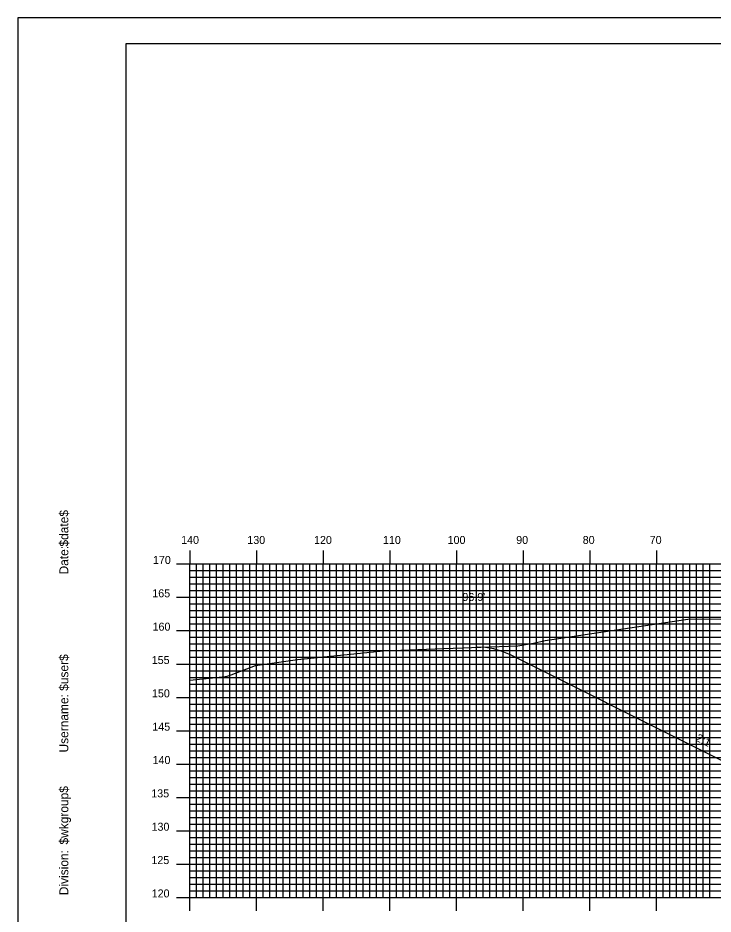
# Model space of a CAD drawing. Extents: x 1785008 to 1785352, y 442591 to 442811.
# Drawn here: x 1785008.2 to 1785112.5, y 442676.2 to 442810.5 of the extents above; entities that cross this region are included whole.
import ezdxf

# ---------------------------------------------------------------- set-up
doc = ezdxf.new("R2010")
doc.units = 0
for name, color, linetype in [('ANNOTATION', 7, 'Continuous'), ('BORDER', 7, 'Continuous'), ('D_Roadway_SlopeLines', 7, 'Continuous'), ('D_Text_Standard', 7, 'Continuous'), ('H_V ANNOTATION', 7, 'Continuous'), ('MAJOR', 7, 'Continuous'), ('MINOR', 7, 'Continuous'), ('PLOT BOUNDARY', 7, 'Continuous'), ('S_Roadway_Centerline', 7, 'Continuous')]:
    doc.layers.add(name, color=color, linetype=linetype)

msp = doc.modelspace()

# ---------------------------------------------------------------- linework, layer by layer
at = {"layer": 'BORDER'}
msp.add_lwpolyline([(1785024.43, 442596.67), (1785344.43, 442596.67), (1785344.43, 442806.67), (1785024.43, 442806.67)], close=True, dxfattribs=at)
at = {"layer": 'D_Roadway_SlopeLines'}
msp.add_lwpolyline([(1785139.85, 442686.16), (1785082.14, 442715.02), (1785080.89, 442715.56), (1785079.64, 442715.93), (1785078.39, 442716.14), (1785077.14, 442716.18)], dxfattribs=at)
at = {"layer": 'MAJOR'}
for p, q in [((1785034.03, 442730.67), (1785034.03, 442728.67)), ((1785044.03, 442730.67), (1785044.03, 442728.67)), ((1785054.03, 442730.67), (1785054.03, 442728.67)), ((1785064.03, 442730.67), (1785064.03, 442728.67)), ((1785074.03, 442730.67), (1785074.03, 442728.67)), ((1785084.03, 442730.67), (1785084.03, 442728.67)), ((1785094.03, 442730.67), (1785094.03, 442728.67)), ((1785104.03, 442730.67), (1785104.03, 442728.67)), ((1785032.02, 442728.67), (1785034.03, 442728.67)), ((1785034.03, 442728.67), (1785314.03, 442728.67)), ((1785034.03, 442678.67), (1785034.03, 442728.67)), ((1785034.03, 442678.67), (1785034.03, 442728.67)), ((1785034.03, 442728.67), (1785314.03, 442728.67)), ((1785044.03, 442678.67), (1785044.03, 442728.67)), ((1785054.03, 442678.67), (1785054.03, 442728.67)), ((1785064.03, 442678.67), (1785064.03, 442728.67)), ((1785074.03, 442678.67), (1785074.03, 442728.67)), ((1785084.03, 442678.67), (1785084.03, 442728.67)), ((1785094.03, 442678.67), (1785094.03, 442728.67)), ((1785104.03, 442678.67), (1785104.03, 442728.67)), ((1785032.02, 442723.67), (1785034.03, 442723.67)), ((1785034.03, 442723.67), (1785314.03, 442723.67)), ((1785032.02, 442718.67), (1785034.03, 442718.67)), ((1785034.03, 442718.67), (1785314.03, 442718.67)), ((1785032.02, 442713.67), (1785034.03, 442713.67)), ((1785034.03, 442713.67), (1785314.03, 442713.67)), ((1785032.02, 442708.67), (1785034.03, 442708.67)), ((1785034.03, 442708.67), (1785314.03, 442708.67)), ((1785032.02, 442703.67), (1785034.03, 442703.67)), ((1785034.03, 442703.67), (1785314.03, 442703.67)), ((1785032.02, 442698.67), (1785034.03, 442698.67)), ((1785034.03, 442698.67), (1785314.03, 442698.67)), ((1785032.02, 442693.67), (1785034.03, 442693.67)), ((1785034.03, 442693.67), (1785314.03, 442693.67)), ((1785032.02, 442688.67), (1785034.03, 442688.67)), ((1785034.03, 442688.67), (1785314.03, 442688.67)), ((1785032.02, 442683.67), (1785034.03, 442683.67)), ((1785034.03, 442683.67), (1785314.03, 442683.67)), ((1785032.02, 442678.67), (1785034.03, 442678.67)), ((1785034.03, 442678.67), (1785314.03, 442678.67)), ((1785034.03, 442678.67), (1785314.03, 442678.67)), ((1785034.03, 442676.66), (1785034.03, 442678.67)), ((1785044.03, 442676.66), (1785044.03, 442678.67)), ((1785054.03, 442676.66), (1785054.03, 442678.67)), ((1785064.03, 442676.66), (1785064.03, 442678.67)), ((1785074.03, 442676.66), (1785074.03, 442678.67)), ((1785084.03, 442676.66), (1785084.03, 442678.67)), ((1785094.03, 442676.66), (1785094.03, 442678.67)), ((1785104.03, 442676.66), (1785104.03, 442678.67))]:
    msp.add_line(p, q, dxfattribs=at)
at = {"layer": 'MINOR'}
for p, q in [((1785035.03, 442678.67), (1785035.03, 442728.67)), ((1785036.03, 442678.67), (1785036.03, 442728.67)), ((1785037.03, 442678.67), (1785037.03, 442728.67)), ((1785038.03, 442678.67), (1785038.03, 442728.67)), ((1785039.03, 442678.67), (1785039.03, 442728.67)), ((1785040.03, 442678.67), (1785040.03, 442728.67)), ((1785041.03, 442678.67), (1785041.03, 442728.67)), ((1785042.03, 442678.67), (1785042.03, 442728.67)), ((1785043.03, 442678.67), (1785043.03, 442728.67)), ((1785045.03, 442678.67), (1785045.03, 442728.67)), ((1785046.03, 442678.67), (1785046.03, 442728.67)), ((1785047.03, 442678.67), (1785047.03, 442728.67)), ((1785048.03, 442678.67), (1785048.03, 442728.67)), ((1785049.03, 442678.67), (1785049.03, 442728.67)), ((1785050.03, 442678.67), (1785050.03, 442728.67)), ((1785051.03, 442678.67), (1785051.03, 442728.67)), ((1785052.03, 442678.67), (1785052.03, 442728.67)), ((1785053.03, 442678.67), (1785053.03, 442728.67)), ((1785055.03, 442678.67), (1785055.03, 442728.67)), ((1785056.03, 442678.67), (1785056.03, 442728.67)), ((1785057.03, 442678.67), (1785057.03, 442728.67)), ((1785058.03, 442678.67), (1785058.03, 442728.67)), ((1785059.03, 442678.67), (1785059.03, 442728.67)), ((1785060.03, 442678.67), (1785060.03, 442728.67)), ((1785061.03, 442678.67), (1785061.03, 442728.67)), ((1785062.03, 442678.67), (1785062.03, 442728.67)), ((1785063.03, 442678.67), (1785063.03, 442728.67)), ((1785065.03, 442678.67), (1785065.03, 442728.67)), ((1785066.03, 442678.67), (1785066.03, 442728.67)), ((1785067.03, 442678.67), (1785067.03, 442728.67)), ((1785068.03, 442678.67), (1785068.03, 442728.67)), ((1785069.03, 442678.67), (1785069.03, 442728.67)), ((1785070.03, 442678.67), (1785070.03, 442728.67)), ((1785071.03, 442678.67), (1785071.03, 442728.67)), ((1785072.03, 442678.67), (1785072.03, 442728.67)), ((1785073.03, 442678.67), (1785073.03, 442728.67)), ((1785075.03, 442678.67), (1785075.03, 442728.67)), ((1785076.03, 442678.67), (1785076.03, 442728.67)), ((1785077.03, 442678.67), (1785077.03, 442728.67)), ((1785078.03, 442678.67), (1785078.03, 442728.67)), ((1785079.03, 442678.67), (1785079.03, 442728.67)), ((1785080.03, 442678.67), (1785080.03, 442728.67)), ((1785081.03, 442678.67), (1785081.03, 442728.67)), ((1785082.03, 442678.67), (1785082.03, 442728.67)), ((1785083.03, 442678.67), (1785083.03, 442728.67)), ((1785085.03, 442678.67), (1785085.03, 442728.67)), ((1785086.03, 442678.67), (1785086.03, 442728.67)), ((1785087.03, 442678.67), (1785087.03, 442728.67)), ((1785088.03, 442678.67), (1785088.03, 442728.67)), ((1785089.03, 442678.67), (1785089.03, 442728.67)), ((1785090.03, 442678.67), (1785090.03, 442728.67)), ((1785091.03, 442678.67), (1785091.03, 442728.67)), ((1785092.03, 442678.67), (1785092.03, 442728.67)), ((1785093.03, 442678.67), (1785093.03, 442728.67)), ((1785095.03, 442678.67), (1785095.03, 442728.67)), ((1785096.03, 442678.67), (1785096.03, 442728.67)), ((1785097.03, 442678.67), (1785097.03, 442728.67)), ((1785098.03, 442678.67), (1785098.03, 442728.67)), ((1785099.03, 442678.67), (1785099.03, 442728.67)), ((1785100.03, 442678.67), (1785100.03, 442728.67)), ((1785101.03, 442678.67), (1785101.03, 442728.67)), ((1785102.03, 442678.67), (1785102.03, 442728.67)), ((1785103.03, 442678.67), (1785103.03, 442728.67)), ((1785105.03, 442678.67), (1785105.03, 442728.67)), ((1785106.03, 442678.67), (1785106.03, 442728.67)), ((1785107.03, 442678.67), (1785107.03, 442728.67)), ((1785108.03, 442678.67), (1785108.03, 442728.67)), ((1785109.03, 442678.67), (1785109.03, 442728.67)), ((1785110.03, 442678.67), (1785110.03, 442728.67)), ((1785111.03, 442678.67), (1785111.03, 442728.67)), ((1785112.03, 442678.67), (1785112.03, 442728.67)), ((1785034.03, 442727.67), (1785314.03, 442727.67)), ((1785034.03, 442727.67), (1785036.03, 442727.67)), ((1785034.03, 442726.67), (1785314.03, 442726.67)), ((1785034.03, 442726.67), (1785036.03, 442726.67)), ((1785034.03, 442725.67), (1785314.03, 442725.67)), ((1785034.03, 442725.67), (1785036.03, 442725.67)), ((1785034.03, 442724.67), (1785314.03, 442724.67)), ((1785034.03, 442724.67), (1785036.03, 442724.67)), ((1785034.03, 442722.67), (1785314.03, 442722.67)), ((1785034.03, 442722.67), (1785036.03, 442722.67)), ((1785034.03, 442721.67), (1785314.03, 442721.67)), ((1785034.03, 442721.67), (1785036.03, 442721.67)), ((1785034.03, 442720.67), (1785314.03, 442720.67)), ((1785034.03, 442720.67), (1785036.03, 442720.67)), ((1785034.03, 442719.67), (1785314.03, 442719.67)), ((1785034.03, 442719.67), (1785036.03, 442719.67)), ((1785034.03, 442717.67), (1785314.03, 442717.67)), ((1785034.03, 442717.67), (1785036.03, 442717.67)), ((1785034.03, 442716.67), (1785314.03, 442716.67)), ((1785034.03, 442716.67), (1785036.03, 442716.67)), ((1785034.03, 442715.67), (1785314.03, 442715.67)), ((1785034.03, 442715.67), (1785036.03, 442715.67)), ((1785034.03, 442714.67), (1785314.03, 442714.67)), ((1785034.03, 442714.67), (1785036.03, 442714.67)), ((1785034.03, 442712.67), (1785314.03, 442712.67)), ((1785034.03, 442712.67), (1785036.03, 442712.67)), ((1785034.03, 442711.67), (1785314.03, 442711.67)), ((1785034.03, 442711.67), (1785036.03, 442711.67)), ((1785034.03, 442710.67), (1785314.03, 442710.67)), ((1785034.03, 442710.67), (1785036.03, 442710.67)), ((1785034.03, 442709.67), (1785314.03, 442709.67)), ((1785034.03, 442709.67), (1785036.03, 442709.67)), ((1785034.03, 442707.67), (1785314.03, 442707.67)), ((1785034.03, 442707.67), (1785036.03, 442707.67)), ((1785034.03, 442706.67), (1785314.03, 442706.67)), ((1785034.03, 442706.67), (1785036.03, 442706.67)), ((1785034.03, 442705.67), (1785314.03, 442705.67)), ((1785034.03, 442705.67), (1785036.03, 442705.67)), ((1785034.03, 442704.67), (1785314.03, 442704.67)), ((1785034.03, 442704.67), (1785036.03, 442704.67)), ((1785034.03, 442702.67), (1785314.03, 442702.67)), ((1785034.03, 442702.67), (1785036.03, 442702.67)), ((1785034.03, 442701.67), (1785314.03, 442701.67)), ((1785034.03, 442701.67), (1785036.03, 442701.67)), ((1785034.03, 442700.67), (1785314.03, 442700.67)), ((1785034.03, 442700.67), (1785036.03, 442700.67)), ((1785034.03, 442699.67), (1785314.03, 442699.67)), ((1785034.03, 442699.67), (1785036.03, 442699.67)), ((1785034.03, 442697.67), (1785314.03, 442697.67)), ((1785034.03, 442697.67), (1785036.03, 442697.67)), ((1785034.03, 442696.67), (1785314.03, 442696.67)), ((1785034.03, 442696.67), (1785036.03, 442696.67)), ((1785034.03, 442695.67), (1785314.03, 442695.67)), ((1785034.03, 442695.67), (1785036.03, 442695.67)), ((1785034.03, 442694.67), (1785314.03, 442694.67)), ((1785034.03, 442694.67), (1785036.03, 442694.67)), ((1785034.03, 442692.67), (1785314.03, 442692.67)), ((1785034.03, 442692.67), (1785036.03, 442692.67)), ((1785034.03, 442691.67), (1785314.03, 442691.67)), ((1785034.03, 442691.67), (1785036.03, 442691.67)), ((1785034.03, 442690.67), (1785314.03, 442690.67)), ((1785034.03, 442690.67), (1785036.03, 442690.67)), ((1785034.03, 442689.67), (1785314.03, 442689.67)), ((1785034.03, 442689.67), (1785036.03, 442689.67)), ((1785034.03, 442687.67), (1785036.03, 442687.67)), ((1785034.03, 442687.67), (1785314.03, 442687.67)), ((1785034.03, 442686.67), (1785314.03, 442686.67)), ((1785034.03, 442686.67), (1785036.03, 442686.67)), ((1785034.03, 442685.67), (1785314.03, 442685.67)), ((1785034.03, 442685.67), (1785036.03, 442685.67)), ((1785034.03, 442684.67), (1785314.03, 442684.67)), ((1785034.03, 442684.67), (1785036.03, 442684.67)), ((1785034.03, 442682.67), (1785314.03, 442682.67)), ((1785034.03, 442682.67), (1785036.03, 442682.67)), ((1785034.03, 442681.67), (1785314.03, 442681.67)), ((1785034.03, 442681.67), (1785036.03, 442681.67)), ((1785034.03, 442680.67), (1785314.03, 442680.67)), ((1785034.03, 442680.67), (1785036.03, 442680.67)), ((1785034.03, 442679.67), (1785314.03, 442679.67)), ((1785034.03, 442679.67), (1785036.03, 442679.67))]:
    msp.add_line(p, q, dxfattribs=at)
at = {"layer": 'PLOT BOUNDARY'}
msp.add_lwpolyline([(1785008.24, 442590.55), (1785348.24, 442590.55), (1785348.24, 442810.55), (1785008.24, 442810.55)], close=True, dxfattribs=at)
at = {"layer": 'S_Roadway_Centerline'}
msp.add_lwpolyline([(1785034.03, 442711.26), (1785038.45, 442711.69), (1785039.31, 442711.79), (1785039.47, 442711.8), (1785040.22, 442712.04), (1785043.89, 442713.46), (1785050.2, 442714.32), (1785063.09, 442715.65), (1785072.15, 442716), (1785083.25, 442716.39), (1785085.59, 442716.8), (1785087.36, 442717.18), (1785108.74, 442720.4), (1785113.79, 442720.45)], dxfattribs=at)

# ---------------------------------------------------------------- texts
at = {"layer": 'ANNOTATION'}
msp.add_text('2:1', height=1.2, rotation=333.4349, dxfattribs=at).set_placement((1785109.83, 442702.21))
at = {"layer": 'BORDER'}
for s, p in [('$date$', (1785015.8, 442731.28)), ('$date$', (1785015.8, 442731.28)), ('Date:', (1785015.8, 442727.1)), ('Date:', (1785015.8, 442727.1)), ('$user$', (1785015.8, 442709.65)), ('$user$', (1785015.8, 442709.65)), ('Username:', (1785015.8, 442700.4)), ('Username:', (1785015.8, 442700.4)), ('$wkgroup$', (1785015.8, 442686.6)), ('$wkgroup$', (1785015.8, 442686.6)), ('Division:', (1785015.8, 442679)), ('Division:', (1785015.8, 442679))]:
    msp.add_text(s, height=1.339, rotation=90, dxfattribs=at).set_placement(p)
at = {"layer": 'D_Text_Standard'}
msp.add_text("96.9'", height=1.2, dxfattribs=at).set_placement((1785074.93, 442723.12))
at = {"layer": 'H_V ANNOTATION'}
for s, p in [('140', (1785032.73, 442731.67)), ('130', (1785042.66, 442731.67)), ('120', (1785052.67, 442731.67)), ('110', (1785063.01, 442731.67)), ('100', (1785072.71, 442731.67)), ('90', (1785083, 442731.67)), ('80', (1785092.98, 442731.67)), ('70', (1785103.03, 442731.67)), ('170', (1785028.5, 442728.67)), ('165', (1785028.4, 442723.67)), ('160', (1785028.44, 442718.67)), ('155', (1785028.32, 442713.67)), ('150', (1785028.35, 442708.67)), ('145', (1785028.4, 442703.67)), ('140', (1785028.44, 442698.67)), ('135', (1785028.25, 442693.67)), ('130', (1785028.29, 442688.67)), ('125', (1785028.27, 442683.67)), ('120', (1785028.31, 442678.67))]:
    msp.add_text(s, height=1.2, dxfattribs=at).set_placement(p)
at = {"layer": 'MAJOR'}
msp.add_text('-', height=0.012, dxfattribs=at).set_placement((1785034.02, 442678.67))

doc.saveas('drawing.dxf')
